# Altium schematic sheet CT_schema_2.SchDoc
size 306 x 169 mm
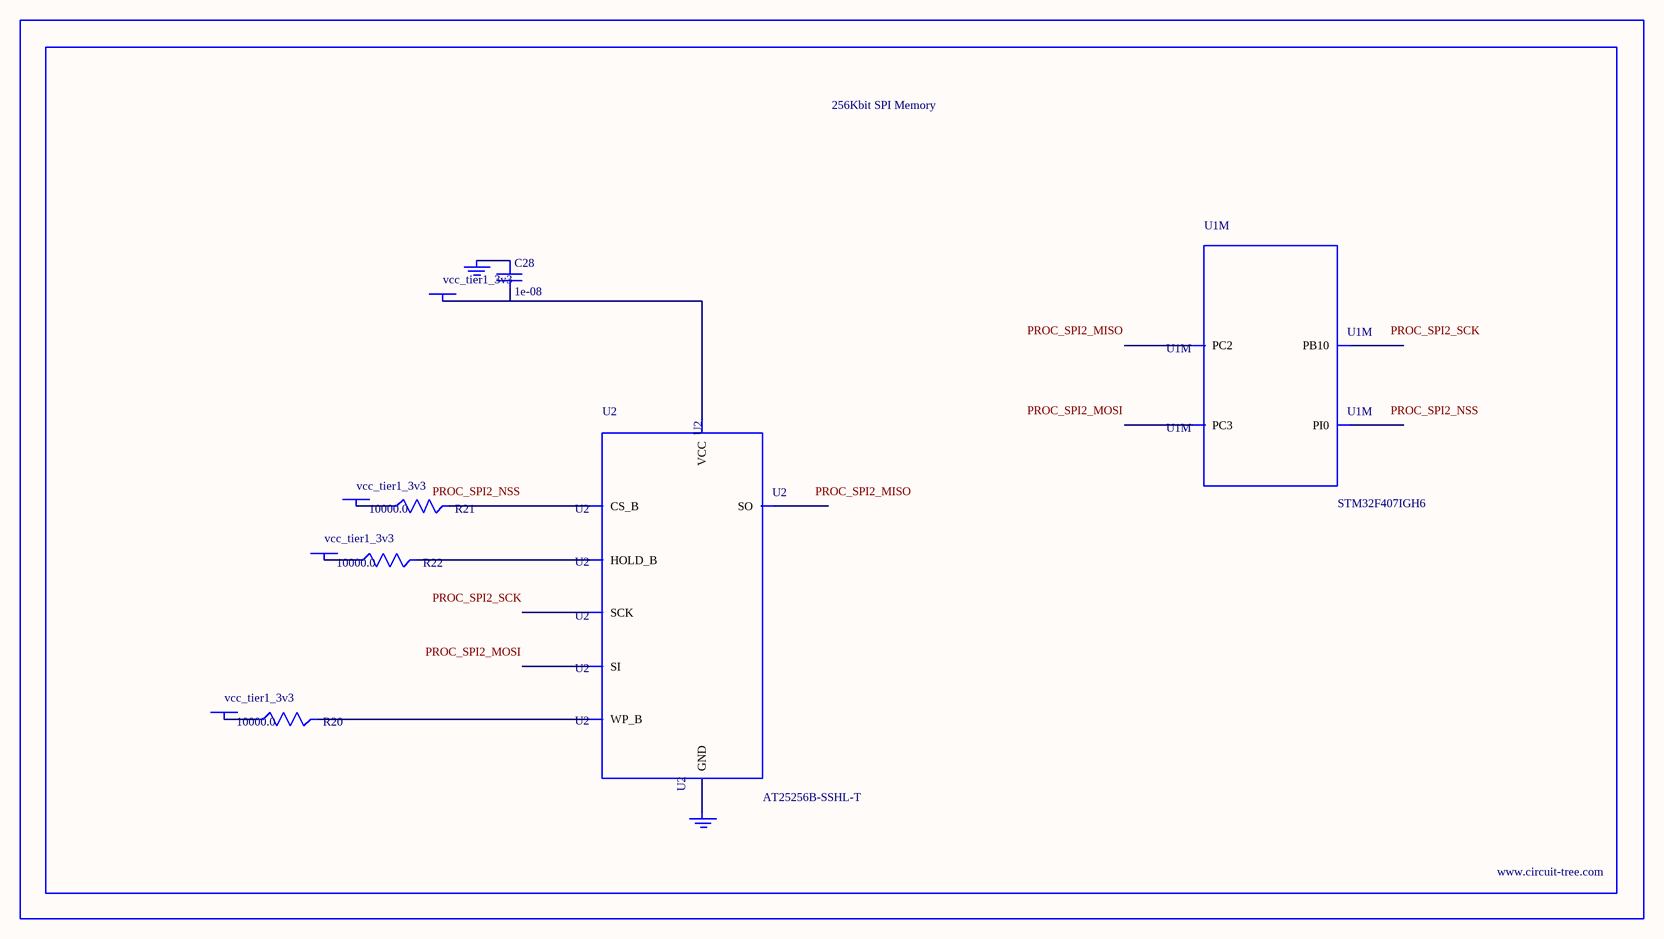
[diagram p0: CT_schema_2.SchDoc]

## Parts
BORDER1  (no value)
C28  1e-08  [C0402]
GND_INSTANCE_1_0  (no value)
GND_INSTANCE_1_1  (no value)
POWER_INSTANCE_1_0  vcc_tier1_3v3
POWER_INSTANCE_1_1  vcc_tier1_3v3
POWER_INSTANCE_1_2  vcc_tier1_3v3
POWER_INSTANCE_1_3  vcc_tier1_3v3
R20  10000.0  [R0603]
R21  10000.0  [R0603]
R22  10000.0  [R0603]
U1  STM32F407IGH6  [UFBGA176]  (part M of 18)
U2  AT25256B-SSHL-T  [SOIC-8]

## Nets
NetC28_1: C28.1 GND_INSTANCE_1_0.0(GND)
NetC28_2: C28.2 POWER_INSTANCE_1_3.0(PWR) U2.8(VCC)
NetGND_INSTANCE_1_1_0: GND_INSTANCE_1_1.0(GND) U2.4(GND)
NetPOWER_INSTANCE_1_0_0: POWER_INSTANCE_1_0.0(PWR) R21.1
NetPOWER_INSTANCE_1_1_0: POWER_INSTANCE_1_1.0(PWR) R20.1
NetPOWER_INSTANCE_1_2_0: POWER_INSTANCE_1_2.0(PWR) R22.1
NetR20_2: R20.2 U2.3(WP_B)
NetR21_2: R21.2 U2.1(CS_B)
NetR22_2: R22.2 U2.7(HOLD_B)

Not connected (* = marked no-connect by the designer): U1 E14(PI0) M4(PC2) M5(PC3) R12(PB10); U2 2(SO) 5(SI) 6(SCK)

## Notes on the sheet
- Labels drawn without touching a wire or pin: PROC_SPI2_MISO, PROC_SPI2_MOSI, PROC_SPI2_NSS, PROC_SPI2_SCK

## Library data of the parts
BORDER1 = BORDER_PAGE1
C28 = C0402C103K3RAC
GND_INSTANCE_1_0 GND_INSTANCE_1_1 = GND
POWER_INSTANCE_1_0-POWER_INSTANCE_1_3 = PWR
R20-R22 = RC0603JR-0710KL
